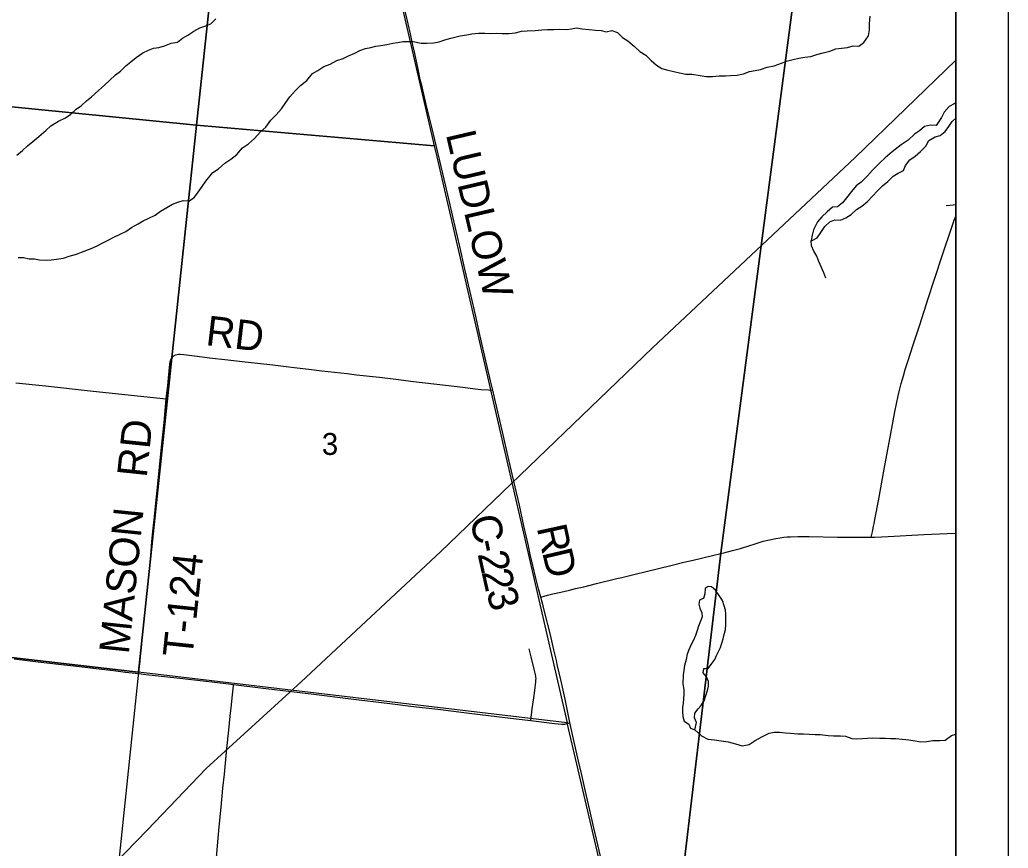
# Model space of a CAD drawing. Extents: x 831 to 1552, y 430 to 870.
# Drawn here: x 1046.09 to 1083.77, y 664.2 to 695.8 of the extents above; entities that cross this region are included whole.
import ezdxf

# ---------------------------------------------------------------- set-up
doc = ezdxf.new("R2010")
doc.units = 0
for name, color, linetype in [('GM_X_Corporation', 7, 'Continuous'), ('GM_X_County_Road', 7, 'Continuous'), ('GM_X_County_Road_Text', 7, 'Continuous'), ('GM_X_Minor_Lake', 7, 'Continuous'), ('GM_X_Minor_River', 7, 'Continuous'), ('GM_X_Rail_Line', 7, 'Continuous'), ('GM_X_Section_Text', 7, 'Continuous'), ('GM_X_State_Route', 7, 'Continuous'), ('GM_X_Township_Road', 7, 'Continuous'), ('GM_X_Township_Road_Text', 7, 'Continuous'), ('SH_Data', 7, 'Continuous')]:
    doc.layers.add(name, color=color, linetype=linetype)

msp = doc.modelspace()

# ---------------------------------------------------------------- linework, layer by layer
at = {"layer": 'GM_X_Corporation'}
msp.add_lwpolyline([(957.479, 781.045), (956.56, 771.006), (955.451, 760.717), (953.653, 740.871), (952.689, 730.885), (949.971, 703.401), (947.763, 681.071), (945.766, 658.183), (945.766, 650.938), (1069.909, 650.938), (1070.34, 654.531), (1072.813, 675.454), (1078.126, 715.958), (1081.227, 740.59), (1081.766, 744.853), (1081.766, 786.938)], dxfattribs=at)
for points in [[(1069.909, 650.938), (1081.766, 650.938), (1081.766, 744.853), (1081.227, 740.59), (1078.126, 715.958), (1072.813, 675.454), (1070.34, 654.531)], [(1034.738, 712.834), (1054.834, 710.548), (1052.831, 691.774), (1032.694, 693.772)], [(1054.834, 710.548), (1057.444, 710.279), (1058.309, 706.633), (1059.895, 699.645), (1061.888, 690.989), (1052.831, 691.774)], [(1032.694, 693.772), (1052.831, 691.774), (1050.619, 670.912), (1030.47, 673.244)], [(1052.831, 691.774), (1061.888, 690.989), (1061.986, 690.566), (1066.955, 668.986), (1050.619, 670.912)], [(1030.47, 673.244), (1050.619, 670.912), (1048.583, 651.419), (1028.346, 653.321)], [(1052.227, 650.938), (1070.052, 650.938), (1070.404, 654.192), (1066.955, 668.986), (1050.619, 670.912), (1048.583, 651.419)]]:
    msp.add_lwpolyline(points, close=True, dxfattribs=at)
at = {"layer": 'GM_X_County_Road'}
for points in [[(1061.073, 694.835), (1060.978, 695.259), (1060.802, 696.022), (1060.658, 696.652), (1060.492, 697.405), (1060.418, 697.732), (1060.343, 698.059), (1060.196, 698.687), (1060.121, 699.001), (1060.016, 699.448), (1059.92, 699.859), (1059.759, 700.562), (1059.599, 701.252), (1059.507, 701.639), (1059.434, 701.954), (1059.313, 702.487), (1059.125, 703.311), (1059.017, 703.796), (1058.85, 704.535), (1058.736, 705.044), (1058.632, 705.504), (1058.458, 706.242), (1058.323, 706.828)], [(1064.115, 681.67), (1064.028, 682.027), (1063.816, 682.96), (1063.629, 683.784), (1063.455, 684.548), (1063.296, 685.251), (1063.059, 686.293), (1062.859, 687.152), (1062.593, 688.29), (1062.452, 688.908), (1062.263, 689.719), (1062.098, 690.42), (1061.96, 691.001), (1061.79, 691.701), (1061.585, 692.57), (1061.422, 693.246), (1061.356, 693.524), (1061.273, 693.912), (1061.147, 694.507), (1061.073, 694.835)], [(1065.952, 673.774), (1065.864, 674.097), (1065.754, 674.505), (1065.643, 674.989), (1065.55, 675.402), (1065.476, 675.729), (1065.302, 676.492), (1065.132, 677.282), (1064.971, 677.985), (1064.73, 679.013), (1064.484, 680.079), (1064.385, 680.515), (1064.183, 681.387), (1064.115, 681.67)], [(1078.546, 676.064), (1078.684, 676.071), (1079.189, 676.096), (1080.551, 676.168), (1081.443, 676.206), (1081.766, 676.218)]]:
    msp.add_lwpolyline(points, dxfattribs=at)
at = {"layer": 'GM_X_Minor_Lake'}
for points in [[(1081.766, 692.63), (1081.711, 692.596), (1081.519, 692.491), (1081.319, 692.279), (1081.226, 692.067), (1081.018, 691.772), (1080.797, 691.782), (1080.576, 691.73), (1080.384, 691.565), (1080.193, 691.437), (1079.947, 691.211), (1079.679, 691.023), (1079.341, 690.767), (1079.08, 690.533), (1078.888, 690.352), (1078.589, 690.066), (1078.396, 689.847), (1078.166, 689.605), (1077.967, 689.462), (1077.797, 689.243), (1077.597, 689.009), (1077.451, 688.812), (1077.259, 688.662), (1077.068, 688.648), (1076.869, 688.475), (1076.662, 688.286), (1076.492, 688.09), (1076.345, 687.787), (1076.297, 687.589), (1076.258, 687.384), (1076.258, 687.379)], [(1076.258, 687.379), (1076.288, 687.376), (1076.479, 687.488), (1076.626, 687.685), (1076.78, 687.912), (1076.972, 688.093), (1077.163, 688.168), (1077.368, 688.15), (1077.575, 688.248), (1077.782, 688.375), (1077.989, 688.564), (1078.18, 688.691), (1078.403, 688.864), (1078.595, 689.076), (1078.787, 689.272), (1078.979, 689.461), (1079.171, 689.626), (1079.379, 689.838), (1079.57, 689.943), (1079.769, 690.047), (1079.854, 690.245), (1080.016, 690.456), (1080.223, 690.599), (1080.423, 690.772), (1080.622, 690.984), (1080.739, 691.196), (1080.976, 691.331), (1081.167, 691.382), (1081.366, 691.533), (1081.497, 691.722), (1081.628, 691.919), (1081.766, 692.043)], [(1071.821, 668.714), (1071.886, 668.994), (1071.805, 669.177), (1071.815, 669.352), (1071.947, 669.517), (1072.055, 669.637), (1072.171, 669.818), (1072.242, 670.029), (1072.298, 670.218), (1072.339, 670.385), (1072.341, 670.56), (1072.26, 670.735), (1072.133, 670.889), (1072.166, 671.056), (1072.333, 671.061), (1072.472, 671.249), (1072.581, 671.399), (1072.651, 671.55), (1072.738, 671.731), (1072.793, 671.86), (1072.832, 671.988), (1072.904, 672.192), (1072.944, 672.351), (1072.984, 672.541), (1073.003, 672.738), (1073.008, 673.133), (1072.988, 673.285), (1072.944, 673.452), (1072.871, 673.643), (1072.745, 673.842), (1072.611, 674.042), (1072.454, 674.173), (1072.332, 674.182), (1072.21, 674.108), (1072.199, 673.903), (1072.151, 673.729), (1072.072, 673.695)], [(1072.072, 673.695), (1071.998, 673.663), (1071.973, 673.504), (1072.017, 673.351), (1072.083, 673.183), (1072.095, 673.024), (1072.04, 672.857), (1071.954, 672.676), (1071.906, 672.51), (1071.842, 672.313), (1071.756, 672.117), (1071.67, 671.951), (1071.592, 671.77), (1071.528, 671.596), (1071.495, 671.399), (1071.431, 671.172), (1071.406, 670.983), (1071.373, 670.809), (1071.368, 670.452), (1071.403, 670.254), (1071.4, 670.087), (1071.383, 669.897), (1071.373, 669.73), (1071.355, 669.571), (1071.345, 669.411), (1071.358, 669.229), (1071.408, 669.046), (1071.589, 668.937), (1071.655, 668.777), (1071.821, 668.714)]]:
    msp.add_lwpolyline(points, dxfattribs=at)
at = {"layer": 'GM_X_Minor_River'}
for points in [[(1062.874, 695.191), (1063.126, 695.227), (1063.324, 695.263), (1063.575, 695.283), (1063.819, 695.288), (1064.032, 695.279), (1064.268, 695.284), (1064.482, 695.274), (1064.725, 695.28), (1064.984, 695.3), (1065.213, 695.359), (1065.427, 695.372), (1065.739, 695.384), (1065.983, 695.42), (1066.204, 695.433), (1066.44, 695.423), (1066.676, 695.444), (1066.927, 695.434), (1067.125, 695.455), (1067.316, 695.491), (1067.521, 695.451), (1067.787, 695.425), (1068.039, 695.408), (1068.244, 695.391), (1068.441, 695.343), (1068.663, 695.394), (1068.868, 695.309), (1069.064, 695.124), (1069.261, 694.993), (1069.518, 694.778), (1069.729, 694.593), (1069.949, 694.454), (1070.16, 694.246), (1070.364, 694.07), (1070.568, 693.946), (1070.796, 693.883), (1071.024, 693.827), (1071.237, 693.78), (1071.48, 693.724), (1071.708, 693.722), (1072.028, 693.674), (1072.248, 693.633), (1072.492, 693.639), (1072.743, 693.659), (1072.995, 693.665), (1073.185, 693.67), (1073.437, 693.691), (1073.673, 693.742), (1073.91, 693.831), (1074.116, 693.867), (1074.322, 693.903), (1074.581, 693.985), (1074.848, 694.043), (1075.123, 694.14), (1075.314, 694.214), (1075.566, 694.28), (1075.787, 694.331), (1076.009, 694.375), (1076.237, 694.403), (1076.474, 694.477), (1076.711, 694.536), (1076.97, 694.602), (1077.199, 694.691), (1077.405, 694.712), (1077.634, 694.741), (1077.855, 694.8), (1078.068, 694.798), (1078.26, 694.933), (1078.445, 695.182), (1078.477, 695.418), (1078.472, 695.646), (1078.505, 695.935)], [(1045.975, 690.635), (1046.19, 690.808), (1046.389, 690.988), (1046.581, 691.154), (1046.811, 691.342), (1047.087, 691.575), (1047.279, 691.756), (1047.57, 691.935), (1047.83, 692.062), (1048.037, 692.204), (1048.245, 692.393), (1048.444, 692.528), (1048.636, 692.701), (1048.828, 692.866), (1049.096, 693.107), (1049.319, 693.302), (1049.526, 693.498), (1049.734, 693.701), (1049.925, 693.836), (1050.133, 694.047), (1050.324, 694.19), (1050.532, 694.355), (1050.777, 694.535), (1050.991, 694.64), (1051.182, 694.714), (1051.388, 694.742), (1051.609, 694.808), (1051.861, 694.905), (1052.098, 694.948), (1052.297, 695.098), (1052.489, 695.218), (1052.726, 695.36), (1052.948, 695.495), (1053.147, 695.561), (1053.368, 695.65), (1053.568, 695.831)], [(1046.023, 686.729), (1046.237, 686.735), (1046.442, 686.687), (1046.647, 686.685), (1046.837, 686.645), (1047.089, 686.635), (1047.287, 686.648), (1047.493, 686.668), (1047.759, 686.711), (1047.966, 686.778), (1048.248, 686.859), (1048.447, 686.94), (1048.806, 687.074), (1049.02, 687.163), (1049.234, 687.275), (1049.456, 687.387), (1049.678, 687.507), (1049.915, 687.626), (1050.137, 687.723), (1050.351, 687.88), (1050.596, 688.015), (1050.787, 688.127), (1050.986, 688.216), (1051.254, 688.351), (1051.453, 688.493), (1051.698, 688.636), (1051.905, 688.763), (1052.119, 688.844), (1052.317, 688.911), (1052.553, 688.893), (1052.745, 689.028), (1052.884, 689.225), (1053.038, 689.436), (1053.184, 689.641), (1053.454, 689.98), (1053.668, 690.108), (1053.906, 690.326), (1054.129, 690.483), (1054.359, 690.656), (1054.574, 690.92), (1054.811, 691.063), (1055.042, 691.273), (1055.257, 691.507), (1055.472, 691.703), (1055.657, 691.967), (1055.857, 692.171), (1056.065, 692.397), (1056.227, 692.647), (1056.389, 692.858), (1056.604, 693.099), (1056.796, 693.288), (1057.026, 693.483), (1057.249, 693.747), (1057.448, 693.86), (1057.678, 694.017), (1057.923, 694.106), (1058.175, 694.24), (1058.412, 694.322), (1058.618, 694.419), (1058.855, 694.523), (1059.054, 694.627), (1059.268, 694.701), (1059.474, 694.737), (1059.665, 694.789), (1059.856, 694.817), (1060.084, 694.861), (1060.306, 694.912), (1060.504, 694.933), (1060.702, 694.969), (1060.893, 694.974), (1061.083, 694.973), (1061.395, 694.909), (1061.608, 694.907), (1061.874, 694.919), (1062.08, 694.963), (1062.286, 695.029), (1062.515, 695.096), (1062.874, 695.191)], [(1081.401, 688.718), (1081.667, 688.737), (1081.766, 688.751)], [(1076.816, 685.947), (1076.741, 686.146), (1076.547, 686.574), (1076.465, 686.78), (1076.353, 686.979), (1076.271, 687.178), (1076.258, 687.379)], [(1071.821, 668.714), (1072.076, 668.482), (1072.317, 668.365), (1072.567, 668.331), (1072.825, 668.297), (1073.09, 668.263), (1073.37, 668.183), (1073.62, 668.111), (1073.886, 668.153), (1074.124, 668.31), (1074.376, 668.45), (1074.659, 668.583), (1074.849, 668.626), (1075.062, 668.623), (1075.267, 668.605), (1075.471, 668.587), (1075.752, 668.56), (1075.957, 668.558), (1076.177, 668.547), (1076.405, 668.536), (1076.602, 668.534), (1076.905, 668.499), (1077.103, 668.489), (1077.368, 668.493), (1077.558, 668.475), (1077.807, 668.388), (1077.997, 668.378), (1078.217, 668.39), (1078.407, 668.403), (1078.597, 668.408), (1078.87, 668.396), (1079.091, 668.401), (1079.28, 668.391), (1079.478, 668.38), (1079.728, 668.362), (1079.978, 668.336), (1080.22, 668.294), (1080.433, 668.261), (1080.668, 668.265), (1080.896, 668.308), (1081.162, 668.304), (1081.367, 668.317), (1081.605, 668.503), (1081.766, 668.546)]]:
    msp.add_lwpolyline(points, dxfattribs=at)
at = {"layer": 'GM_X_Rail_Line'}
msp.add_lwpolyline([(1049.69, 663.597), (1050.96, 664.907), (1053.197, 667.241), (1056.818, 670.545), (1062.12, 675.501), (1070.208, 683.291), (1077.928, 690.548), (1081.766, 694.259)], dxfattribs=at)
at = {"layer": 'GM_X_State_Route'}
for points in [[(1072.817, 675.443), (1072.924, 675.468), (1073.262, 675.55), (1073.56, 675.632), (1073.879, 675.735), (1074.115, 675.814), (1074.424, 675.908), (1074.667, 675.968), (1074.907, 676.015), (1075.072, 676.042), (1075.214, 676.06), (1075.341, 676.072), (1075.468, 676.082), (1075.743, 676.091), (1076.178, 676.09), (1077.259, 676.071), (1077.636, 676.064), (1077.982, 676.062), (1078.348, 676.061), (1078.546, 676.064), (1078.589, 676.271), (1078.631, 676.482), (1078.651, 676.581), (1078.691, 676.802), (1078.815, 677.449), (1079.04, 678.658), (1079.293, 680.014), (1079.449, 680.845), (1079.571, 681.455), (1079.63, 681.722), (1079.684, 681.927), (1079.768, 682.222), (1079.843, 682.464), (1079.937, 682.76), (1080.142, 683.398), (1080.391, 684.167), (1080.718, 685.171), (1080.936, 685.832), (1081.29, 686.916), (1081.585, 687.817), (1081.705, 688.157), (1081.766, 688.304)], [(1065.952, 673.774), (1066.199, 673.847), (1066.405, 673.902), (1066.714, 673.973), (1067.047, 674.049), (1067.276, 674.102), (1067.584, 674.176), (1068.073, 674.294), (1068.845, 674.483), (1069.04, 674.531), (1069.492, 674.64), (1070.015, 674.766), (1070.389, 674.853), (1070.956, 674.997), (1071.403, 675.105), (1071.763, 675.192), (1072.488, 675.367), (1072.817, 675.443)], [(1045.88, 671.423), (1046.793, 671.312), (1047.57, 671.219), (1048.372, 671.126), (1049.002, 671.053), (1049.656, 670.976), (1050.124, 670.92), (1050.628, 670.861), (1050.891, 670.83), (1052.073, 670.7), (1053.196, 670.573), (1053.948, 670.478), (1054.242, 670.443), (1055.367, 670.308), (1056.02, 670.225), (1057.303, 670.072), (1058.708, 669.894), (1060.201, 669.715), (1061.102, 669.61), (1062.027, 669.499), (1063.223, 669.349), (1063.951, 669.264), (1065.012, 669.137), (1065.572, 669.068), (1066.472, 668.961), (1066.745, 668.937), (1066.825, 668.933), (1066.869, 668.937), (1066.909, 668.943), (1066.975, 668.962), (1067.059, 668.99), (1066.873, 669.892), (1066.722, 670.57), (1066.576, 671.211), (1066.542, 671.356), (1066.482, 671.61), (1066.446, 671.767), (1066.314, 672.335), (1066.205, 672.78), (1066.178, 672.889), (1066.064, 673.334), (1066.037, 673.442), (1066.002, 673.582), (1065.952, 673.774)], [(1070.344, 654.52), (1070.319, 654.632), (1069.998, 656.076), (1069.752, 657.218), (1068.986, 660.587), (1068.675, 661.931), (1068.551, 662.476), (1068.414, 663.082), (1067.971, 664.982), (1067.809, 665.697), (1067.657, 666.364), (1067.497, 667.054), (1067.391, 667.527), (1067.214, 668.315), (1067.059, 668.99)]]:
    msp.add_lwpolyline(points, dxfattribs=at)
at = {"layer": 'GM_X_Township_Road'}
for points in [[(1051.668, 681.345), (1051.679, 681.439), (1051.693, 681.554), (1051.728, 681.837), (1051.761, 682.132), (1051.808, 682.665), (1051.822, 682.753), (1051.844, 682.827), (1051.861, 682.863), (1051.896, 682.917), (1051.942, 682.964), (1051.979, 682.991), (1052.031, 683.019), (1052.094, 683.037), (1052.145, 683.045), (1052.209, 683.048), (1052.348, 683.035), (1052.854, 682.972), (1053.322, 682.911), (1054.023, 682.83), (1054.68, 682.754), (1055.73, 682.638), (1056.544, 682.54), (1057.111, 682.469), (1057.605, 682.411), (1058.568, 682.302), (1058.926, 682.26), (1059.795, 682.162), (1060.421, 682.091), (1061.099, 682.007), (1062.766, 681.812), (1063.666, 681.702), (1063.956, 681.678), (1064.115, 681.67)], [(1045.934, 681.954), (1047.071, 681.833), (1048.776, 681.648), (1050.815, 681.434), (1051.668, 681.345)], [(1050.628, 670.861), (1050.643, 671.004), (1050.657, 671.149), (1050.673, 671.319), (1050.692, 671.54), (1050.724, 671.835), (1050.77, 672.33), (1050.81, 672.726), (1050.838, 672.985), (1050.928, 673.85), (1050.981, 674.369), (1051.079, 675.371), (1051.129, 675.903), (1051.179, 676.398), (1051.224, 676.843), (1051.287, 677.486), (1051.322, 677.844), (1051.495, 679.501), (1051.589, 680.441), (1051.668, 681.345)], [(1065.572, 669.068), (1065.624, 669.523), (1065.681, 669.94), (1065.716, 670.211), (1065.76, 670.543), (1065.766, 670.609), (1065.77, 670.668), (1065.766, 670.719), (1065.761, 670.765), (1065.751, 670.819), (1065.739, 670.875), (1065.702, 671.031), (1065.588, 671.5), (1065.512, 671.802)], [(1053.576, 663.694), (1053.649, 664.586), (1053.693, 665.019), (1053.764, 665.761), (1053.835, 666.491), (1053.893, 667.022), (1053.943, 667.579), (1053.988, 667.999), (1054.052, 668.704), (1054.11, 669.236), (1054.157, 669.67), (1054.187, 669.941), (1054.212, 670.17), (1054.237, 670.395), (1054.242, 670.443)]]:
    msp.add_lwpolyline(points, dxfattribs=at)
at = {"layer": 'SH_Data'}
for p, q in [((1083.766, 788.938), (1083.766, 648.938)), ((1081.766, 786.938), (1081.766, 650.938))]:
    msp.add_line(p, q, dxfattribs=at)

# ---------------------------------------------------------------- texts
at = {"layer": 'GM_X_County_Road_Text'}
for s, height, rotation, p in [('LUDLOW', 1.1364, 283.1781, (1062.324, 691.435)), ('C', 1.136, 282.2193, (1063.237, 676.802)), ('R', 1.136, 282.3188, (1065.791, 676.429)), ('-', 1.136, 282.2508, (1063.435, 675.889)), ('D', 1.136, 283.3325, (1065.995, 675.496)), ('2', 1.136, 282.3056, (1063.534, 675.431)), ('2', 1.136, 282.5964, (1063.685, 674.741)), ('3', 1.136, 286.3022, (1063.857, 673.981))]:
    msp.add_text(s, height=height, rotation=rotation, dxfattribs=at).set_placement(p)
at = {"layer": 'GM_X_Section_Text'}
msp.add_text('3', height=0.837, rotation=0, dxfattribs=at).set_placement((1057.604, 679.202))
at = {"layer": 'GM_X_Township_Road_Text'}
for s, rotation, p in [('RD', 353.1707, (1053.145, 683.394)), ('RD', 84.0932, (1050.926, 678.313)), ('MASON', 84.139, (1050.243, 671.578)), ('T-124', 83.9617, (1052.666, 671.446))]:
    msp.add_text(s, height=1.1364, rotation=rotation, dxfattribs=at).set_placement(p)

doc.saveas('drawing.dxf')
